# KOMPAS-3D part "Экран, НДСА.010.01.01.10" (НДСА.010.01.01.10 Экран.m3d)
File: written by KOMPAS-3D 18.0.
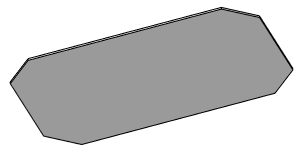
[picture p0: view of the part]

Document properties: Автор: Пользователь Windows; Полное имя файла: F:\Temp\НДСА.010.01.01.10 Экран.m3d

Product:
- Part/product: Экран  | designation НДСА.010.01.01.10
    Материал: Сталь 12Х18Н10Т ГОСТ 5632-72 (density 7900 kg/m3)
    Масса: 0.024979
    additional columns: <item xmlns="http://appius.ru/pdm" xmlns:xs="http://www.w3.org/2001/XMLSchema" x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; <item xmlns="http://appius.ru/pdm" xmlns:xs="http://www.w3.org/2001/XMLSchema" x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; <item xmlns="http://appius.ru/pdm" xmlns:xs="http://www.w3.org/2001/XMLSchema" x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; <item xmlns="http://appius.ru/pdm" xmlns:xs="http://www.w3.org/2001/XMLSchema" x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; <item xmlns="http://appius.ru/pdm" xmlns:xs="http://www.w3.org/2001/XMLSchema" x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; <item xmlns="http://appius.ru/pdm" xmlns:xs="http://www.w3.org/2001/XMLSchema" x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; <item xmlns="http://appius.ru/pdm" xmlns:xs="http://www.w3.org/2001/XMLSchema" x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

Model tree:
1. Эскиз:1
2. Операция выдавливания:1
     Расстояние 1 = 0.7
3. Фаска:1  (with: Операция выдавливания:1)  (labels: Сталь 12Х18Н10Т ГОСТ 5632-72; SYSTEM_PROPERTY_ADDITIONAL_FOR:9.000000)
     Угол = 45; Длина 1 = 10; Длина 2 = 10

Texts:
  НДСА.010.01.01.10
